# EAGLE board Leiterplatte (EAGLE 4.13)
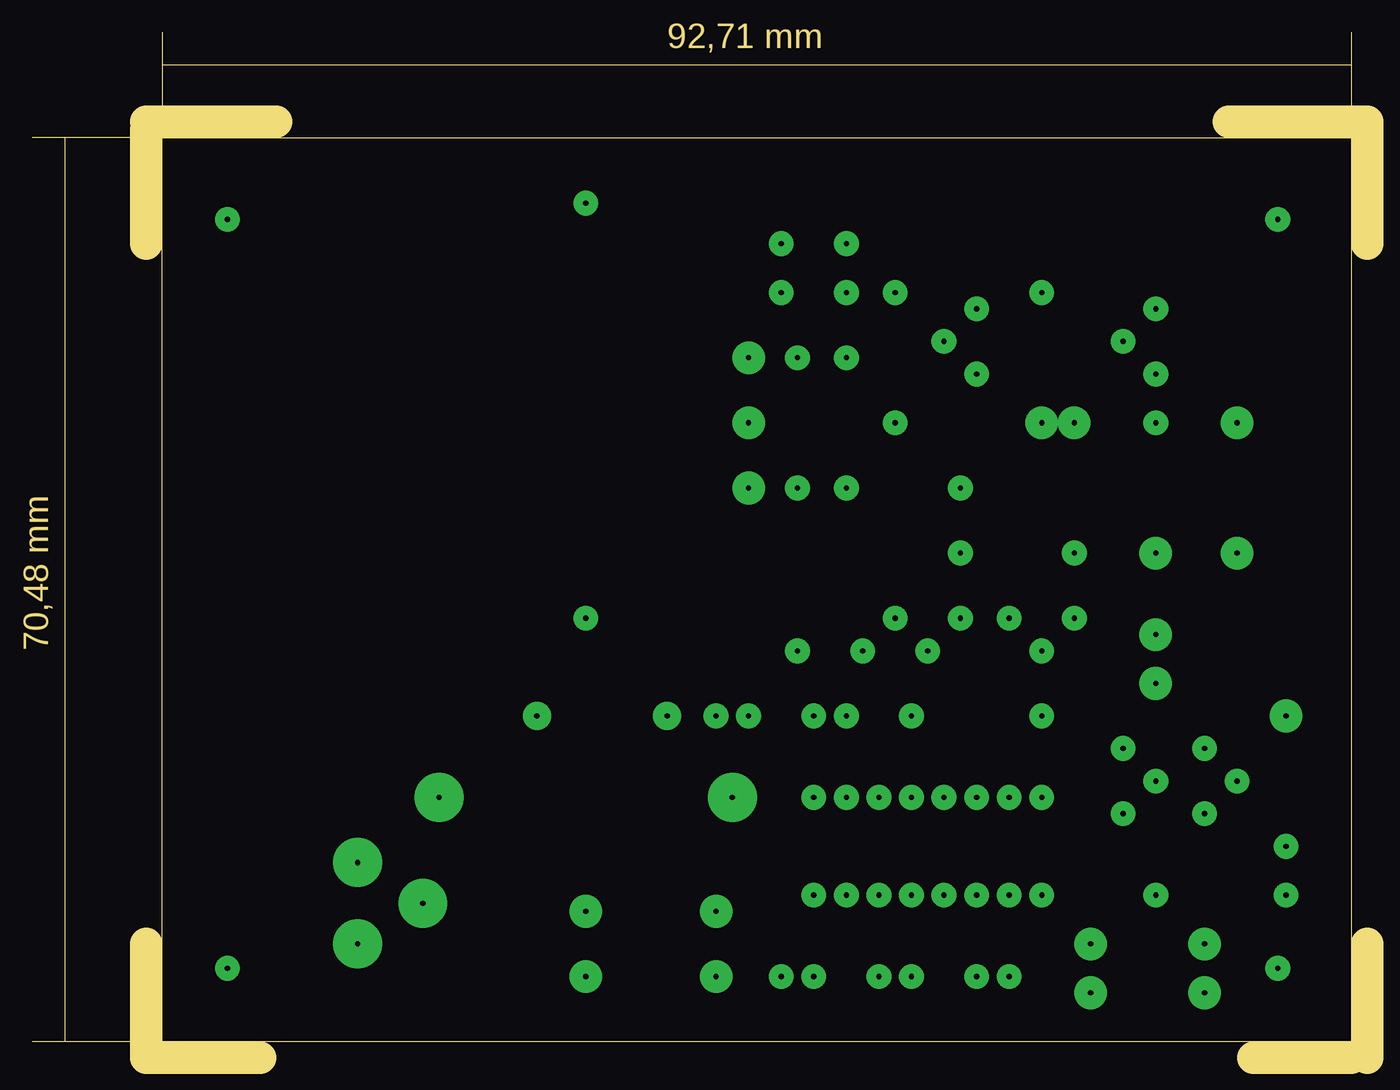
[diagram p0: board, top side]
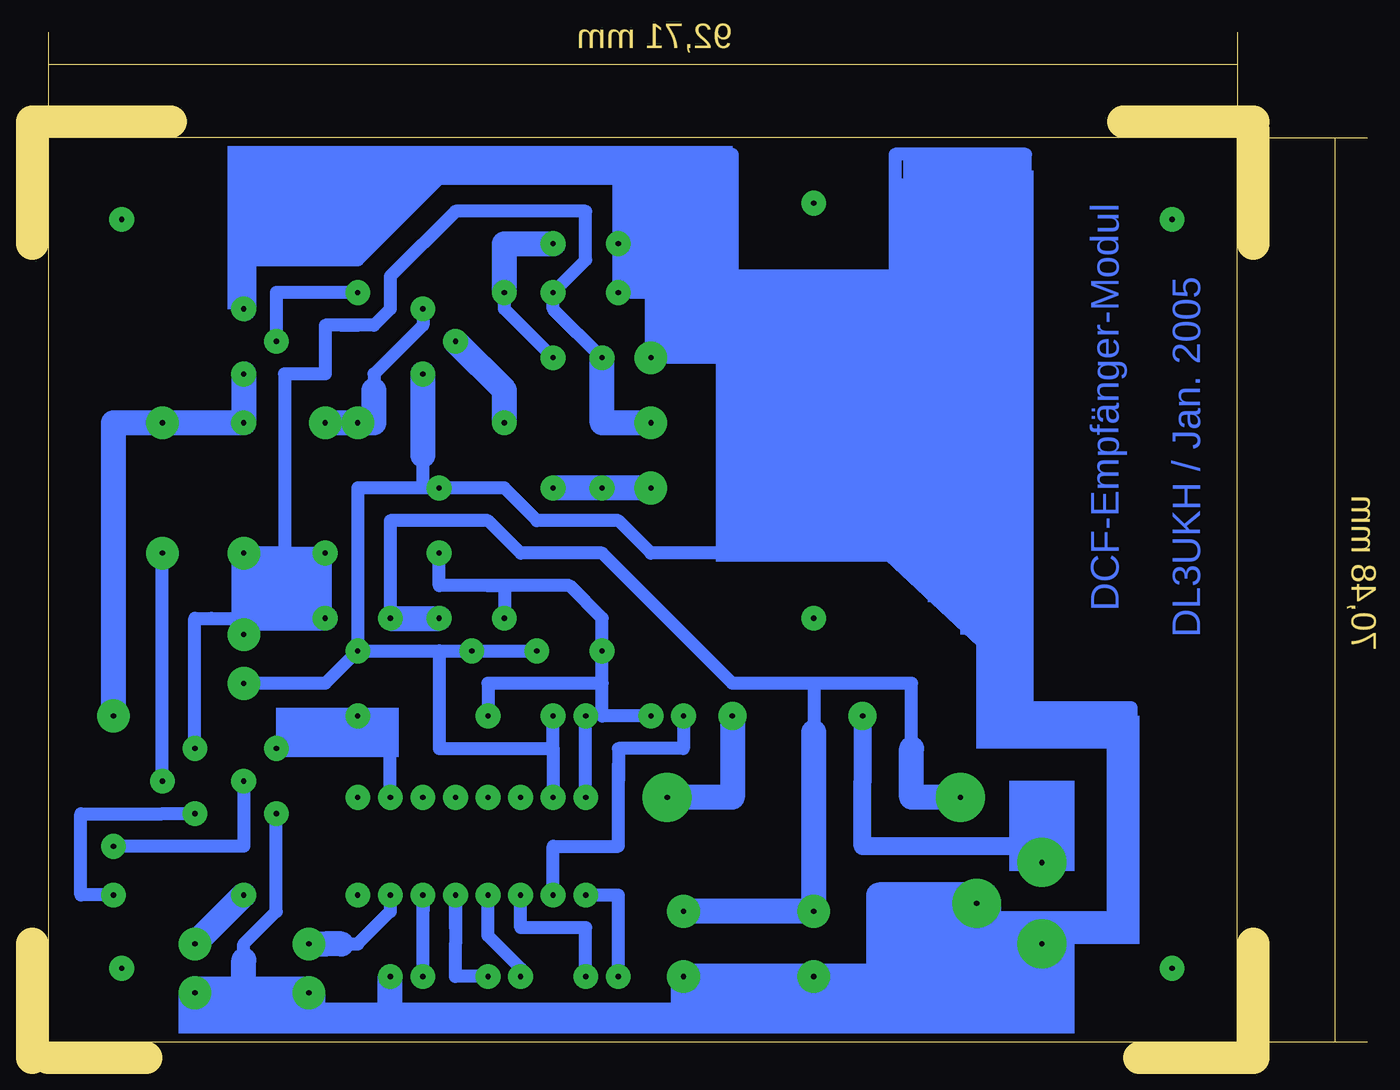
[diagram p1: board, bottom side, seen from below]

Size 104.14 x 80.01 mm. Coordinates in mm from the lower left corner, seen from the top.
Outline: 10.16,71.75 102.87,71.75 102.87,1.27 10.16,1.27
Outline: 10.16,1.27 10.16,71.75
Outline: 8.89,8.89 8.89,0 17.78,0
Outline: 8.89,72.39 8.89,63.5
Outline: 102.87,0 95.25,0
Outline: 104.14,0 104.14,8.89
Outline: 104.14,72.39 104.14,63.5
Outline: 8.89,73.02 19.05,73.02
Outline: 104.14,72.71 104.14,73.02 93.34,73.02
Outline: 10.16,71.75 2.54,71.75
Outline: 2.54,71.75 0,71.75
Outline: 10.16,1.27 2.54,1.27
Outline: 2.54,1.27 0,1.27
Outline: 2.54,71.75 2.54,1.27
Outline: 10.16,80.01 10.16,77.47
Outline: 10.16,77.47 10.16,72.39
Outline: 102.87,80.01 102.87,77.47
Outline: 102.87,77.47 102.87,72.39
Outline: 10.16,77.47 102.87,77.47
Copper layers (1*16): Top 0.035mm / dielectric 1.5mm / Bottom 0.035mm
Design rules "default": minimum track width 10mil, minimum drill 24mil, track to track 8mil, track to pad 8mil, pad to pad 8mil, via to via 8mil, smd to smd 8mil, copper to edge 40mil, drill to drill 8mil, minimum pad ring 10mil, minimum via ring 8mil, stop-mask expansion 4mil, vias tented up to drill 0mil, thermal gap 10mil

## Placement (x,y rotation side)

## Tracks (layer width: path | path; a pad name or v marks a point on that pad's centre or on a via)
S$1  (via drill 0.41 pad 1.93)
  other vias: 15.24,6.98
S$2  (via drill 0.41 pad 1.93)
  other vias: 97.16,6.98
S$3  (via drill 0.41 pad 1.93)
  other vias: 97.16,65.41
S$4  (via drill 0.41 pad 1.93)
  other vias: 15.24,65.41
S$6  (via drill 0.41 pad 2.18)
  Bottom 1.422: 25.4,16.51 39.37,16.51 39.37,21.59 v39.37,26.67
S$7  (via drill 0.41 pad 1.93)
  other vias: 43.18,34.29
S$8  (via drill 0.41 pad 1.93)
  other vias: 43.18,66.67
S$9  (via drill 0.41 pad 3.81)
  Bottom 1.93: v25.4,15.24 26.67,16.51
S$10
  Bottom 1.016: 20.32,10.79 23.5,10.79
S$11  (via drill 0.41 pad 3.81)
  other vias: 30.48,12.06
S$12  (via drill 0.41 pad 1.93)
  Bottom 1.016: v53.34,26.67 53.34,24.13 58.42,24.13 58.42,21.59 | 58.42,21.59 58.42,22.86 | v63.5,12.7 63.5,16.51 58.42,16.51 58.42,21.59
S$13  (via drill 0.41 pad 2.18, 0.41 pad 3.81)
  Bottom 1.93: v49.53,26.67 49.53,20.32 v54.61,20.32
S$14  (via drill 0.41 pad 1.93, 0.41 pad 2.54, 0.41 pad 3.81)
  Bottom 1.016: v72.39,34.29 v76.2,34.29 76.2,41.91 68.58,41.91 66.04,39.37 59.69,39.37 49.53,29.21 46.99,29.21 | 43.18,29.21 43.18,25.4 | 46.99,29.21 48.26,29.21 | 43.18,29.21 35.56,29.21 35.56,24.13 | 43.18,29.21 46.99,29.21
  Bottom 1.93: v53.34,11.43 v43.18,11.43 43.18,25.4 | v31.75,20.32 35.56,20.32 35.56,24.13 | v76.2,34.29 v72.39,34.29
S$15
  Bottom 1.93: 27.94,31.11 38.1,40.64
S$16  (via drill 0.41 pad 1.93, 0.41 pad 2.54)
  Bottom 1.016: v55.88,44.45 v59.69,44.45 v63.5,44.45
  Bottom 1.93: v55.88,44.45 v63.5,44.45
S$17  (via drill 0.41 pad 1.93)
  Bottom 1.93: v71.12,55.88 67.31,52.07 v67.31,49.53
S$18  (via drill 0.41 pad 1.93)
  Bottom 1.016: v60.96,6.35 60.96,10.16 66.04,10.16 v66.04,12.7
S$19  (via drill 0.41 pad 1.93)
  other vias: 85.09,19.05
S$20  (via drill 0.41 pad 1.93)
  Bottom 1.016: 73.66,11.43 v73.66,12.7 v73.66,6.35
S$21  (via drill 0.41 pad 1.93)
  Bottom 1.016: v63.5,54.61 67.31,58.42 v67.31,59.69
  Bottom 1.93: v63.5,63.5 67.31,63.5 v67.31,59.69
S$22  (via drill 0.41 pad 1.93, 0.41 pad 2.54, 0.41 pad 3.81)
  Bottom 1.016: 85.09,19.05 85.09,11.43 87.63,8.89 87.63,7.62 | 87.63,3.81 87.63,5.08 | 87.63,3.81 82.55,3.81 76.2,3.81 53.34,3.81 | 87.63,3.81 91.44,3.81 v91.44,5.08
  Bottom 1.93: 87.63,5.08 87.63,7.62 | 76.2,3.81 v76.2,6.35 | 53.34,5.08 v53.34,6.35 v43.18,6.35 | v91.44,5.08 v82.55,5.08 | 53.34,5.08 53.34,3.81 43.18,3.81 | 43.18,5.08 53.34,5.08 | 43.18,5.08 43.18,3.81 | 43.18,3.81 25.4,3.81 25.4,5.08 | 43.18,5.08 v43.18,6.35 | 25.4,6.35 38.1,6.35 | 38.1,6.35 v43.18,6.35 | 25.4,6.35 v25.4,8.89 | 25.4,5.08 30.48,5.08 | 30.48,5.08 43.18,5.08 | 25.4,5.08 25.4,6.35 | 30.48,5.08 30.48,7.62 | 30.48,12.06 30.48,12.7 38.1,12.7 38.1,6.35
  Bottom 2.54: 82.55,3.81 v82.55,5.08 v91.44,5.08 | 30.48,8.89 30.48,7.62
  Bottom 3.81: 30.48,12.06 30.48,8.89
S$23  (via drill 0.41 pad 1.93)
  other vias: 78.74,12.7
S$24  (via drill 0.41 pad 1.93)
  Bottom 1.016: v97.79,12.7 100.33,12.7 100.33,19.05 93.98,19.05 v91.44,19.05
S$25  (via drill 0.41 pad 1.93, 0.41 pad 2.54)
  Bottom 1.016: v93.98,21.59 v93.98,39.37
S$26  (via drill 0.41 pad 1.93)
  other vias: 66.04,20.32
S$27  (via drill 0.41 pad 1.93)
  other vias: 68.58,20.32
S$28  (via drill 0.41 pad 1.93)
  other vias: 71.12,20.32
S$29  (via drill 0.41 pad 1.93)
  other vias: 73.66,20.32
S$30  (via drill 0.41 pad 1.93)
  Bottom 1.016: v78.74,26.67 76.2,26.67 76.2,24.13 | v76.2,20.32 76.2,24.13 | 76.2,24.13 v85.09,24.13
S$31  (via drill 0.41 pad 1.93)
  other vias: 78.74,20.32
S$32  (via drill 0.41 pad 1.93)
  Bottom 1.016: v72.39,39.37 72.39,36.83 68.58,36.83 | v67.31,34.29 67.31,36.83 68.58,36.83 | 68.58,36.83 62.23,36.83 59.69,34.29 v59.69,31.75 59.69,29.21 | 59.69,29.21 59.69,26.67 v55.88,26.67 | 59.69,29.21 68.58,29.21 v68.58,26.67
S$33  (via drill 0.41 pad 1.93)
  Bottom 1.016: v60.96,20.32 v60.96,26.67
S$34
  Bottom 1.93: 75.56,69.21 80.01,64.77
S$35  (via drill 0.41 pad 1.93)
  Bottom 1.016: v68.58,12.7 68.58,9.53 66.04,6.98 v66.04,6.35
S$36  (via drill 0.41 pad 1.93)
  Bottom 1.016: v68.58,6.35 71.12,6.35 71.12,8.89 v71.12,12.7 71.12,10.16
S$37  (via drill 0.41 pad 1.93)
  Bottom 1.016: v58.42,6.35 58.42,12.7 v60.96,12.7
S$38  (via drill 0.41 pad 1.93)
  Bottom 1.016: v78.74,59.69 85.09,59.69 v85.09,55.88
S$39  (via drill 0.41 pad 1.93, 0.41 pad 2.54)
  Bottom 1.93: v97.79,26.67 97.79,49.53 v93.98,49.53 v87.63,49.53 v87.63,53.34
S$40  (via drill 0.41 pad 1.93, 0.41 pad 2.54)
  Bottom 1.016: v73.66,58.42 73.66,57.15 77.47,53.34 77.47,52.07 | 80.01,49.53 v81.28,49.53
  Bottom 1.93: v78.74,49.53 77.47,49.53 77.47,52.07 | v78.74,49.53 80.01,49.53 | v78.74,49.53 v81.28,49.53
S$41
  Bottom 1.93: 36.83,40.64 33.02,36.83
S$42  (via drill 0.41 pad 1.93)
  Bottom 1.016: v87.63,21.59 87.63,16.51 v97.79,16.51
S$43  (via drill 0.41 pad 1.93, 0.41 pad 2.54)
  Bottom 1.016: v76.2,12.7 76.2,11.43 78.74,8.89 80.01,8.89
  Bottom 1.93: 80.01,8.89 81.28,8.89 v82.55,8.89
S$44  (via drill 0.41 pad 1.93, 0.41 pad 2.54)
  Bottom 1.93: v87.63,12.7 v91.44,8.89
S$45  (via drill 0.41 pad 1.93, 0.41 pad 2.54)
  Bottom 1.016: 63.5,24.13 v63.5,26.67 | 63.5,24.13 v63.5,20.32 | 63.5,24.13 72.39,24.13 72.39,31.75 | v64.77,31.75 v69.85,31.75 72.39,31.75 | v87.63,29.21 81.28,29.21 v78.74,31.75 | v78.74,31.75 72.39,31.75 | v78.74,31.75 78.74,44.45 73.66,44.45 | 73.66,44.45 73.66,46.99 | 73.66,44.45 v72.39,44.45 67.31,44.45 64.77,41.91 58.42,41.91 55.88,39.37 49.53,39.37 49.53,40.64 | 87.63,63.5 82.55,68.58 78.74,68.58 | v58.42,63.5 v58.42,59.69 55.88,59.69 | 78.74,68.58 78.74,62.23 | 58.42,68.58 73.66,68.58 78.74,68.58 | 58.42,68.58 v58.42,63.5 | 55.88,63.5 v58.42,63.5 | 55.88,59.69 v55.88,54.61 49.53,54.61 | 55.88,59.69 55.88,63.5 | 49.53,54.61 48.26,54.61 | 49.53,54.61 55.88,59.69 | 55.88,68.58 55.88,63.5 | 55.88,68.58 58.42,68.58 | 55.88,68.58 49.53,68.58 49.53,60.96 | 49.53,60.96 49.53,57.15 49.53,70.48 87.63,70.48 | 49.53,60.96 36.83,60.96 36.83,70.48 26.67,70.48 26.67,27.3 18.41,27.3 18.41,12.7 | 78.74,62.23 71.12,69.85 | 78.74,62.23 87.63,62.23
  Bottom 1.93: 73.66,46.99 v73.66,53.34 | 87.63,63.5 87.63,62.23 v87.63,58.42 | 49.53,40.64 49.53,54.61 49.53,57.15 | 73.66,68.58 79.38,62.87
S$47  (via drill 0.41 pad 1.93, 0.41 pad 2.54)
  Bottom 1.016: 91.44,34.29 90.17,34.29 | v91.44,24.13 91.44,34.29 | v81.28,34.29 v81.28,39.37 84.45,39.37 | 84.45,39.37 v87.63,39.37 | 84.45,39.37 84.45,53.34 81.28,53.34 81.28,57.15 80.01,57.15 | 80.01,57.15 78.74,57.15 | 80.01,57.15 77.47,57.15 76.2,58.42 76.2,60.96 71.12,66.04 60.96,66.04 60.96,62.23 v63.5,59.69 63.5,58.42 v59.69,54.61 | 91.44,34.29 87.63,34.29
  Bottom 1.93: 87.63,34.29 v87.63,33.02 | v81.28,34.29 87.63,34.29 | v87.63,39.37 87.63,34.29 | v59.69,54.61 59.69,49.53 v55.88,49.53
S$48
  Bottom 1.016: 50.17,69.21 87.63,69.21
(copper drawn outside any net)
  shapes: Bottom area x42

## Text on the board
Bottom: DCF-Empfänger-Modul | DL3UKH / Jan. 2005
Dimension: 92,71 mm | 70,48 mm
